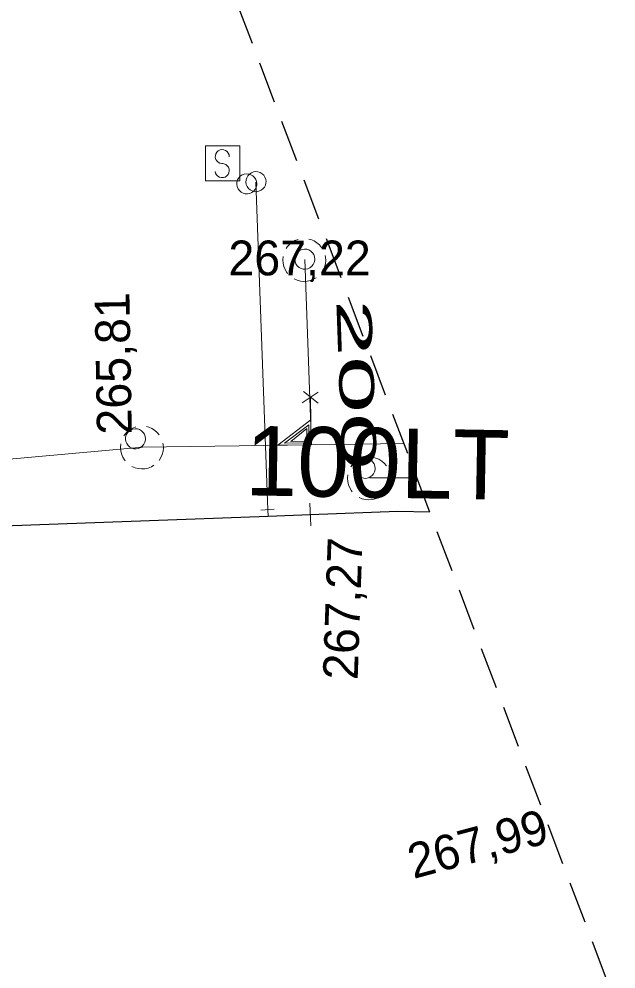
# Model space of a CAD drawing. Extents: x -732074 to -731966, y -1048695 to -1047982.
# Drawn here: x -732000.79 to -731987.06, y -1048554.48 to -1048532.64 of the extents above; entities that cross this region are included whole.
import ezdxf

# ---------------------------------------------------------------- set-up
doc = ezdxf.new("R2010")
doc.units = 0
doc.header["$LTSCALE"] = 0.32
doc.linetypes.add('MEDIUM_DASHED', pattern=[4.5, 3, -1.5])
doc.layers.add('1', color=7, linetype='Continuous')
for name, color, linetype, lineweight in [('18', 7, 'Continuous', 13), ('20', 7, 'Continuous', 13), ('49', 7, 'Continuous', 13), ('63', 7, 'MEDIUM_DASHED', 25), ('8', 7, 'Continuous', 13)]:
    doc.layers.add(name, color=color, linetype=linetype, lineweight=lineweight)

msp = doc.modelspace()

# ---------------------------------------------------------------- linework, layer by layer
at = {"layer": '18'}
for p, q in [((-731993.909, -1048541.214), (-731994.276, -1048541.463)), ((-731994.247, -1048541.206), (-731993.908, -1048541.471))]:
    msp.add_line(p, q, dxfattribs=at)
for points in [[(-731994.372, -1048537.707), (-731994.443, -1048537.735), (-731994.51, -1048537.774), (-731994.57, -1048537.822), (-731994.621, -1048537.879), (-731994.645, -1048537.913)], [(-731993.831, -1048537.89), (-731993.881, -1048537.832), (-731993.939, -1048537.782), (-731994.004, -1048537.741), (-731994.075, -1048537.712), (-731994.124, -1048537.698)], [(-731994.717, -1048538.099), (-731994.723, -1048538.176), (-731994.718, -1048538.253), (-731994.701, -1048538.328), (-731994.672, -1048538.399), (-731994.632, -1048538.465), (-731994.616, -1048538.487)], [(-731993.836, -1048538.476), (-731993.795, -1048538.411), (-731993.764, -1048538.341), (-731993.745, -1048538.266), (-731993.737, -1048538.19), (-731993.742, -1048538.113), (-731993.748, -1048538.078)], [(-731994.459, -1048538.616), (-731994.389, -1048538.647), (-731994.314, -1048538.666), (-731994.238, -1048538.673), (-731994.161, -1048538.668), (-731994.086, -1048538.651), (-731994.014, -1048538.623), (-731993.954, -1048538.588)], [(-731994.085, -1048541.333), (-731994.07, -1048542.428), (-731994.84, -1048542.438), (-731994.078, -1048541.85)], [(-731998.102, -1048542.017), (-731998.173, -1048542.045), (-731998.24, -1048542.084), (-731998.3, -1048542.132), (-731998.351, -1048542.189), (-731998.375, -1048542.223)], [(-731997.561, -1048542.2), (-731997.611, -1048542.142), (-731997.669, -1048542.092), (-731997.734, -1048542.051), (-731997.805, -1048542.022), (-731997.854, -1048542.008)], [(-731994.127, -1048541.97), (-731994.121, -1048542.385), (-731994.687, -1048542.392), (-731994.127, -1048541.968)], [(-731994.173, -1048542.053), (-731994.169, -1048542.345), (-731994.541, -1048542.35), (-731994.172, -1048542.053)], [(-731998.447, -1048542.409), (-731998.453, -1048542.486), (-731998.448, -1048542.563), (-731998.431, -1048542.638), (-731998.402, -1048542.709), (-731998.362, -1048542.775), (-731998.346, -1048542.797)], [(-731997.566, -1048542.786), (-731997.525, -1048542.721), (-731997.494, -1048542.651), (-731997.475, -1048542.576), (-731997.467, -1048542.5), (-731997.472, -1048542.423), (-731997.478, -1048542.388)], [(-731992.883, -1048542.727), (-731992.954, -1048542.755), (-731993.021, -1048542.794), (-731993.081, -1048542.842), (-731993.132, -1048542.899), (-731993.156, -1048542.933)], [(-731992.342, -1048542.91), (-731992.392, -1048542.852), (-731992.45, -1048542.802), (-731992.515, -1048542.761), (-731992.586, -1048542.732), (-731992.635, -1048542.718)], [(-731998.189, -1048542.926), (-731998.119, -1048542.957), (-731998.044, -1048542.976), (-731997.968, -1048542.983), (-731997.891, -1048542.978), (-731997.816, -1048542.961), (-731997.744, -1048542.933), (-731997.684, -1048542.898)], [(-731993.228, -1048543.119), (-731993.233, -1048543.196), (-731993.228, -1048543.273), (-731993.212, -1048543.348), (-731993.183, -1048543.419), (-731993.142, -1048543.485), (-731993.127, -1048543.507)], [(-731992.347, -1048543.496), (-731992.306, -1048543.431), (-731992.275, -1048543.361), (-731992.255, -1048543.286), (-731992.248, -1048543.21), (-731992.253, -1048543.133), (-731992.259, -1048543.098)], [(-731992.97, -1048543.636), (-731992.9, -1048543.667), (-731992.825, -1048543.686), (-731992.749, -1048543.693), (-731992.672, -1048543.688), (-731992.597, -1048543.671), (-731992.525, -1048543.643), (-731992.465, -1048543.608)]]:
    msp.add_lwpolyline(points, dxfattribs=at)
for points in [[(-731993.988, -1048538.159), (-731993.994, -1048538.107), (-731994.012, -1048538.057), (-731994.04, -1048538.013), (-731994.078, -1048537.976), (-731994.123, -1048537.949), (-731994.173, -1048537.933), (-731994.225, -1048537.928), (-731994.277, -1048537.935), (-731994.326, -1048537.954), (-731994.37, -1048537.984), (-731994.405, -1048538.023), (-731994.431, -1048538.068), (-731994.446, -1048538.119), (-731994.449, -1048538.171), (-731994.441, -1048538.223), (-731994.42, -1048538.271), (-731994.39, -1048538.314), (-731994.35, -1048538.349), (-731994.304, -1048538.373), (-731994.253, -1048538.387), (-731994.201, -1048538.389), (-731994.149, -1048538.379), (-731994.101, -1048538.357), (-731994.059, -1048538.325), (-731994.026, -1048538.285), (-731994.002, -1048538.238), (-731993.99, -1048538.187)], [(-731997.878, -1048542.289), (-731997.884, -1048542.237), (-731997.902, -1048542.187), (-731997.93, -1048542.143), (-731997.968, -1048542.106), (-731998.013, -1048542.079), (-731998.063, -1048542.063), (-731998.115, -1048542.058), (-731998.167, -1048542.065), (-731998.216, -1048542.084), (-731998.26, -1048542.114), (-731998.295, -1048542.153), (-731998.321, -1048542.198), (-731998.336, -1048542.249), (-731998.339, -1048542.301), (-731998.331, -1048542.353), (-731998.31, -1048542.401), (-731998.28, -1048542.444), (-731998.24, -1048542.479), (-731998.194, -1048542.503), (-731998.143, -1048542.517), (-731998.091, -1048542.519), (-731998.039, -1048542.509), (-731997.991, -1048542.487), (-731997.949, -1048542.455), (-731997.916, -1048542.415), (-731997.892, -1048542.368), (-731997.88, -1048542.317)], [(-731992.598, -1048542.969), (-731992.604, -1048542.917), (-731992.622, -1048542.867), (-731992.65, -1048542.823), (-731992.688, -1048542.786), (-731992.733, -1048542.759), (-731992.783, -1048542.743), (-731992.835, -1048542.738), (-731992.887, -1048542.745), (-731992.936, -1048542.764), (-731992.98, -1048542.794), (-731993.015, -1048542.833), (-731993.041, -1048542.878), (-731993.056, -1048542.929), (-731993.059, -1048542.981), (-731993.051, -1048543.033), (-731993.03, -1048543.081), (-731993, -1048543.124), (-731992.96, -1048543.159), (-731992.914, -1048543.183), (-731992.863, -1048543.197), (-731992.811, -1048543.199), (-731992.759, -1048543.189), (-731992.711, -1048543.167), (-731992.669, -1048543.135), (-731992.636, -1048543.095), (-731992.612, -1048543.048), (-731992.6, -1048542.997)], [(-731992.598, -1048542.969), (-731992.604, -1048542.917), (-731992.622, -1048542.867), (-731992.65, -1048542.823), (-731992.688, -1048542.786), (-731992.733, -1048542.759), (-731992.783, -1048542.743), (-731992.835, -1048542.738), (-731992.887, -1048542.745), (-731992.936, -1048542.764), (-731992.98, -1048542.794), (-731993.015, -1048542.833), (-731993.041, -1048542.878), (-731993.056, -1048542.929), (-731993.059, -1048542.981), (-731993.051, -1048543.033), (-731993.03, -1048543.081), (-731993, -1048543.124), (-731992.96, -1048543.159), (-731992.914, -1048543.183), (-731992.863, -1048543.197), (-731992.811, -1048543.199), (-731992.759, -1048543.189), (-731992.711, -1048543.167), (-731992.669, -1048543.135), (-731992.636, -1048543.095), (-731992.612, -1048543.048), (-731992.6, -1048542.997)]]:
    msp.add_lwpolyline(points, close=True, dxfattribs=at)
at = {"layer": '20'}
for p, q in [((-731997.949, -1048542.48), (-732006.969, -1048543.29)), ((-731997.949, -1048542.48), (-732006.969, -1048543.29)), ((-731992.73, -1048543.19), (-731991.646, -1048543.19)), ((-731992.73, -1048543.19), (-731991.646, -1048543.19))]:
    msp.add_line(p, q, dxfattribs=at)
msp.add_lwpolyline([(-731991.945, -1048542.399), (-731994.066, -1048542.427), (-731997.949, -1048542.48)], dxfattribs=at)
msp.add_lwpolyline([(-731991.945, -1048542.399), (-731994.066, -1048542.427), (-731997.949, -1048542.48)], dxfattribs=at)
at = {"layer": '49'}
msp.add_line((-731994.219, -1048538.17), (-731994.066, -1048542.427), dxfattribs=at)
msp.add_line((-731994.219, -1048538.17), (-731994.066, -1048542.427), dxfattribs=at)
at = {"layer": '63'}
msp.add_lwpolyline([(-732020.748, -1048466.307), (-731967.071, -1048608.112), (-731967.071, -1048608.113), (-731967.071, -1048608.115), (-731966.405, -1048694.807)], dxfattribs=at)
at = {"layer": '8'}
for p, q in [((-731994.1, -1048543.77), (-731994.079, -1048544.287)), ((-731994.924, -1048543.91), (-731995.228, -1048543.93))]:
    msp.add_line(p, q, dxfattribs=at)
for points in [[(-731996.502, -1048535.559), (-731995.713, -1048535.559), (-731995.713, -1048536.359), (-731996.502, -1048536.359)], [(-731995.319, -1048536.429), (-731995.325, -1048536.377), (-731995.343, -1048536.327), (-731995.371, -1048536.283), (-731995.409, -1048536.246), (-731995.454, -1048536.219), (-731995.504, -1048536.203), (-731995.556, -1048536.198), (-731995.608, -1048536.205), (-731995.657, -1048536.224), (-731995.701, -1048536.254), (-731995.736, -1048536.293), (-731995.762, -1048536.338), (-731995.777, -1048536.389), (-731995.78, -1048536.441), (-731995.772, -1048536.493), (-731995.751, -1048536.541), (-731995.721, -1048536.584), (-731995.681, -1048536.619), (-731995.635, -1048536.643), (-731995.584, -1048536.657), (-731995.532, -1048536.659), (-731995.48, -1048536.649), (-731995.432, -1048536.627), (-731995.39, -1048536.595), (-731995.357, -1048536.555), (-731995.333, -1048536.508), (-731995.321, -1048536.457)], [(-731995.108, -1048536.379), (-731995.115, -1048536.327), (-731995.132, -1048536.277), (-731995.161, -1048536.233), (-731995.199, -1048536.196), (-731995.244, -1048536.169), (-731995.294, -1048536.153), (-731995.346, -1048536.148), (-731995.397, -1048536.155), (-731995.446, -1048536.174), (-731995.49, -1048536.204), (-731995.526, -1048536.243), (-731995.552, -1048536.288), (-731995.566, -1048536.339), (-731995.57, -1048536.391), (-731995.561, -1048536.443), (-731995.541, -1048536.491), (-731995.511, -1048536.534), (-731995.471, -1048536.569), (-731995.424, -1048536.593), (-731995.374, -1048536.607), (-731995.321, -1048536.609), (-731995.27, -1048536.599), (-731995.222, -1048536.577), (-731995.179, -1048536.545), (-731995.147, -1048536.505), (-731995.123, -1048536.458), (-731995.11, -1048536.407)]]:
    msp.add_lwpolyline(points, close=True, dxfattribs=at)
for points in [[(-731995.953, -1048535.805), (-731995.958, -1048535.762), (-731995.975, -1048535.721), (-731996.002, -1048535.687), (-731996.039, -1048535.661), (-731996.08, -1048535.646), (-731996.123, -1048535.643), (-731996.166, -1048535.651), (-731996.205, -1048535.671), (-731996.238, -1048535.7), (-731996.261, -1048535.738), (-731996.272, -1048535.78), (-731996.274, -1048535.823), (-731996.262, -1048535.866), (-731996.24, -1048535.903), (-731996.208, -1048535.934), (-731996.169, -1048535.954), (-731996.127, -1048535.963), (-731996.1, -1048535.963)], [(-731996.276, -1048536.142), (-731996.266, -1048536.185), (-731996.244, -1048536.224), (-731996.213, -1048536.255), (-731996.174, -1048536.276), (-731996.132, -1048536.287), (-731996.088, -1048536.285), (-731996.046, -1048536.272), (-731996.009, -1048536.248), (-731995.98, -1048536.215), (-731995.961, -1048536.175), (-731995.953, -1048536.132), (-731995.956, -1048536.088), (-731995.973, -1048536.047), (-731995.999, -1048536.012), (-731996.034, -1048535.985), (-731996.075, -1048535.968), (-731996.1, -1048535.963)], [(-731995.059, -1048544.07), (-731995.07, -1048543.92), (-731995.34, -1048536.39)]]:
    msp.add_lwpolyline(points, dxfattribs=at)
at = {"layer": '8', "lineweight": 25}
for points in [[(-732001.568, -1048544.306), (-731995.059, -1048544.07), (-731994.09, -1048544.03)], [(-731994.09, -1048544.03), (-731992.079, -1048543.95), (-731991.352, -1048543.966)]]:
    msp.add_lwpolyline(points, dxfattribs=at)

# ---------------------------------------------------------------- texts
at = {"layer": '1'}
msp.add_text('267,22', height=0.8, dxfattribs=at).set_placement((-731995.973, -1048538.533))
for s, height, rotation, p in [('265,81', 0.8, 91, (-731998.192, -1048542.186)), ('100LT ', 1.6, 359, (-731995.593, -1048543.588)), ('267,27', 0.8, 88, (-731993.003, -1048547.841)), ('267,99', 0.8, 15, (-731991.721, -1048552.409))]:
    msp.add_text(s, height=height, rotation=rotation, dxfattribs=at).set_placement(p)
at = {"layer": '1', "width": 2.2}
msp.add_text('200 ', height=0.8, rotation=272, dxfattribs=at).set_placement((-731993.494, -1048539.095))

doc.saveas('drawing.dxf')
